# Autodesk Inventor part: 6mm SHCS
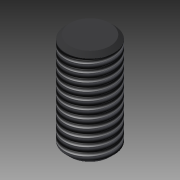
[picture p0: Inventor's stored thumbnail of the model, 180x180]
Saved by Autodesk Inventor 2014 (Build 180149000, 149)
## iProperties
Shininess: 64.0
Angle Display Precision: 2
Document Length Units: 11269
Document Angle Units: 11279
Document Time Units: 11290
Document Mass Units: 11283
Document Length Units Precision: 3
Document Angle Units Precision: 2
Compacted: True
Created: 2002-07
Part Number: 6mm SHCS
Description: 6mm SHCS
Document SubType Name: Modeling
Designer: PN
Density: 1 g/cm^3
Material: Generic
Appearance: 78,78,78
Density: 0.0
Volumn: 0.0
Area: 0.0
PropertySet Name: Model Information
Control State: 0
Master: False
Checked Out: False
Author: PN
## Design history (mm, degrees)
sketch "Sketch1"
  geometry: C1 r 3 at (0, 0); 1 further point
  constraints: 1 centre point, 1 coincident
  dimensions: "d0" = 6 diameter of C1
extrude "Extrusion1" new body sketch "Sketch1" stored distance "d1" = 12; taper "d2" = 0 deg
chamfer "Chamfer1" distance "d3" = 0.5; stored, may be unused: second distance "d4" = 0.5, angle "d21" = 45 deg
sketch "Sketch2"
  geometry: L1 (-1, 1.5)-(-1.866, 0); L2 (1, 1.5)-(-1, 1.5); L3 (-1.866, 0)-(-1, -1.5); L4 (-1, -1.5)-(1, -1.5); L5 (1.866, 0)-(1, 1.5); L6 (1, -1.5)-(1.866, 0); C1 r 2.5 at (0, 0) reference; C2 r 1.616 at (0, 0)
  constraints: 12 end point, 4 tangent, 3 parallel, 1 centre point, 1 coincident, 1 horizontal
  dimensions: "d5" = 3.23205 diameter of C2; "d10" = 1.5 distance from line of C1.centre L2; "d11" = 120 deg angle of L4 L3; "d13" = 120 deg angle of L4 L6; "d16" = 3 distance between parallel lines of L4 L2
extrude "Extrusion2" cut sketch "Sketch2" distance "d17" = 4; taper "d18" = 0 deg
thread "Thread1" dims "d19" = 10, "d20" = 0
body "Solid1"
